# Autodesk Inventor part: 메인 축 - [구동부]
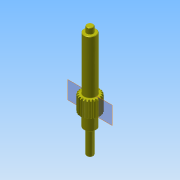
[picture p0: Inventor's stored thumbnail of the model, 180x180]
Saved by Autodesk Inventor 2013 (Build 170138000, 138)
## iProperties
Created: 2016-02
Part Number: 메인 축 - [구동부]
Material: 강철, 연강
Document SubType Name: Modeling
Categories: <?xml version="1.0" encoding="UTF-16"?> <MemberInstance><Categories><FamilyTemplate><FamilyTemplateParameter ValueType="xs:double" Id="1" ObjectReferenceKey="da
Density: 7.86 g/cm^3
Mass: 187.503 g
Surface Area: 82.0529 cm^2
Volume: 23.8554 cm^3
Author: mdu
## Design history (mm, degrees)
sketch "Sketch1"
  geometry: C1 r 12 at (0, 0)
  constraints: 1 centre point
  dimensions: "d0" = 24 diameter of C1 (= da_da)
extrude "Extrusion1" new body sketch "Sketch1" distance "d1" = 20 (= da_b); taper "d2" = 0 deg
workplane "Work Plane2"
feature "피치 지름" dims "d4" = 10, "d5" = 0
workplane "Work Plane8"
workplane "Work Plane9"
chamfer "모따기1" distance "d49" = 1; stored, may be unused: second distance "d50" = 2, angle "d51" = 45 deg
sketch "스케치3"
  geometry: C1 r 7.5 at (0, 0); 1 further point
  constraints: 1 centre point, 1 coincident
  dimensions: "d52" = 15 diameter of C1
extrude "돌출2" join sketch "스케치3" distance "d53" = 66; taper "d54" = 0 deg
sketch "스케치4"
  geometry: C1 r 4 at (0, 0); 1 further point
  constraints: 1 centre point, 1 coincident
  dimensions: "d55" = 8 diameter of C1
extrude "돌출3" join sketch "스케치4" distance "d56" = 7; taper "d57" = 0 deg
sketch "스케치5"
  geometry: C1 r 7.5 at (0, 0) reference; C2 r 7.5 at (0, 0) reference; 1 further point
extrude "돌출4" join sketch "스케치5" distance "d62" = 16; taper "d63" = 0 deg
sketch "스케치6"
  geometry: C1 r 4 at (0, 0); 1 further point
  constraints: 1 centre point, 1 coincident
  dimensions: "d64" = 8 diameter of C1
extrude "돌출5" join sketch "스케치6" distance "d65" = 30; taper "d66" = 0 deg
chamfer "모따기2" distance "d58" = 0.5; stored, may be unused: second distance "d59" = 2, angle "d60" = 45 deg
fillet "모깎기1" dims "d61" = 0.5
feature "스퍼 기어" dims "da_b" = 20, "da_d" = 22, "da_aw" = 31, "da_da" = 24, "da_df" = 19.5, "da_dw" = 22, angle "da_beta" = 0 deg, "da_lefttooth" = 0, "da_righttooth" = 0
sketch "스케치7" dims "d68" = 18
  geometry: C1 r 0.25 at (0, -9); 2 further points
  constraints: 2 vertical alignment, 1 centre point, 1 coincident, 2 other
  dimensions: "d67" = 0.5 diameter of C1
extrude "돌출6" join sketch "스케치7" distance "d69" = 0.3; taper "d70" = 0 deg
body "Solid1"
sketch "Sketch2"
  geometry: C1 r 12 at (0, 0) reference; C2 r 11 at (0, 0)
  constraints: 1 centre point, 1 coincident
  dimensions: "d3" = 22 diameter of C2 (= da_dw)
body "Srf1"
node "투영된 루프1"
other parameters: "d16" = 31 (= da_aw), "d17" = 0, "d34" = 1.428 (computed from da_z), "d39" = 0, "d41" = 0, "d43" = 31 (= da_aw), "d46" = 31 (= da_aw), "d47" = 0, "d48" = 0
